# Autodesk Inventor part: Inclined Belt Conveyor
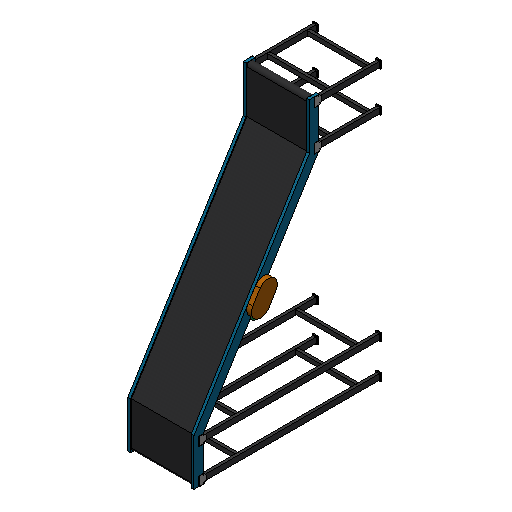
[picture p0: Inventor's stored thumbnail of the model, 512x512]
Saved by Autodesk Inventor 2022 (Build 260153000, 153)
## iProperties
ConnectorClass: Conveyor
family_type: inclined
Created: 2009-10
Part Number: Inclined Belt Conveyor
Document SubType Name: Modeling
Density: 1 g/cm^3
Mass: 74915.2 g
Surface Area: 52834.5 cm^2
Volume: 74915.2 cm^3
Material: 一般
Appearance: 既定
Key Parameters: Width=710.000 mm;UpperHeight=2000.000 mm;LowerHeight=762.000 mm;Length=3000.000 mm;UpperFloatingHeight=0.000 mm;UpperRungNumber=2.000 ul;LowerRungNumber=2.000 u
Title: Inclined Belt Conveyor
Author: Autodesk, Inc.
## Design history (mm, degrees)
body "Solid1"
sketch "Sketch1"
  geometry: L1 (-325, 0)-(325, 0); 2 further points
  constraints: 2 end point, 1 coincident, 1 horizontal, 1 midpoint
  dimensions: "d0" = 650 distance of L1.start L1.end (derived)
workplane "Work Plane1"
sketch "Sketch2"
  geometry: L1 (0, 0)-(0, 2000); L2 (0, 0)-(3000, 0); L3 (3000, 0)-(3000, 762); L4 (0, 2000)-(500, 2000); L5 (500, 2000)-(2500, 762); L6 (2500, 762)-(3000, 762); L7 (0, 2000)-(0, 1900); L8 (3000, 762)-(3000, 662); L9 (471.554, 1900)-(2471.554, 662); L10 (471.554, 1900)-(0, 1900); L11 (2471.554, 662)-(3000, 662)
  constraints: 22 end point, 4 perpendicular, 3 parallel, 2 point on line, 1 vertical
  dimensions: "d1" = 2000 distance of L1.start L1.end (derived); "d2" = 762 distance of L2.end L3.end (derived); "d4" = 500 distance of L1.end L4.end (= EndLength); "d5" = 500 distance of L5.end L3.end (= EndLength); "d6" = 100 distance of L1.end L7.end (= RailHeight); "d7" = 100 distance of L3.end L8.end (= d6); "d8" = 100 distance between parallel lines of L5 L9 (= RailHeight); "d217" = 3000 distance between parallel lines of L3 L1 (derived)
extrude "Rail_1" new body sketch "Sketch2" distance "d9" = 30 (= RailThickness); taper "d10" = 0 deg
mirror "Rail_2"
sketch "Sketch3"
  geometry: L1 (-1288, -2419.054)-(-1288, -2471.554); L2 (-50, 475.946)-(-50, 528.446); L3 (-1288, -2419.054)-(-1288, -1985.777); L4 (-1288, -1985.777)-(-50, 14.223); L5 (-50, 14.223)-(-50, 475.946); L6 (-1238, -2471.554)-(-1338, -2471.554) reference; L7 (0, 0)-(-1238, -2000) reference; L8 (0, 528.446)-(0, 0) reference; L9 (-100, 528.446)-(0, 528.446) reference; L10 (-1238, -2000)-(-1238, -2471.554) reference; L11 (-1338, -1971.554)-(-100, 28.446) reference; L12 (-1338, -2471.554)-(-1338, -1971.554) reference; L13 (-1238, -2471.554)-(-1338, -2471.554) reference; L14 (-1238, -2000)-(-1238, -2471.554) reference; L15 (0, 0)-(-1238, -2000) reference; L16 (0, 528.446)-(0, 0) reference; L17 (-100, 528.446)-(0, 528.446) reference; L18 (-100, 28.446)-(-100, 528.446) reference; L19 (-1338, -1971.554)-(-100, 28.446) reference; L20 (-1238, -2000)-(-1338, -1971.554); L21 (0, 0)-(-100, 28.446); C1 r 30 at (-1288, -2419.054); C2 r 30 at (-50, 475.946); 1 further point
  constraints: 14 end point, 3 midpoint, 3 parallel, 2 centre point, 2 perpendicular
  dimensions: "d11" = 60 diameter of C1; "d12" = 52.5 distance of L1.start L1.end (= 0.5 x RollerGap); "d13" = 60 diameter of C2; "d14" = 52.5 distance of L2.start L2.end (= 0.5 x RollerGap); "StartLength" = 433.27717 distance of L1.start L3.end (derived); "MiddleLength" = 2352.15731 distance of L3.end L4.end (derived); "EndLenght" = 461.72283 distance of L4.end L2.start (derived)
sketch "Sketch6"
  geometry: L1 (0, 0)-(-30, 0) reference; L2 (0, 471.554)-(-30, 471.554) reference; L3 (-29.5, 20)-(-0.5, 20); L4 (-0.5, 20)-(-0.5, 80); L5 (-0.5, 80)-(-29.5, 80); L6 (-29.5, 80)-(-29.5, 20); L7 (-29.5, 391.554)-(-0.5, 391.554); L8 (-0.5, 391.554)-(-0.5, 451.554); L9 (-0.5, 451.554)-(-29.5, 451.554); L10 (-29.5, 451.554)-(-29.5, 391.554); 3 further points
  constraints: 16 end point, 4 parallel, 3 collinear, 2 horizontal, 2 midpoint, 2 perpendicular, 1 vertical alignment
  dimensions: "d18" = 20 distance between parallel lines of L1 L3; "d19" = 60 distance of L5.end L3.start; "d20" = 29 distance of L4.end L5.end; "d21" = 20 distance between parallel lines of L2 L9 (= d18)
workplane "Work Plane3"
extrude "UpperLeg_1" join sketch "Sketch6" taper "d24" = 0 deg; stored distance "d161" = 10
sketch "Sketch7"
  geometry: L1 (0, 0)-(-30, 0) reference; L2 (0, 528.446)-(-30, 528.446) reference; L3 (-29.5, 20)-(-0.5, 20); L4 (-0.5, 20)-(-0.5, 80); L5 (-0.5, 80)-(-29.5, 80); L6 (-29.5, 80)-(-29.5, 20); L7 (-29.5, 448.446)-(-0.5, 448.446); L8 (-0.5, 448.446)-(-0.5, 508.446); L9 (-0.5, 508.446)-(-29.5, 508.446); L10 (-29.5, 508.446)-(-29.5, 448.446); 3 further points
  constraints: 16 end point, 4 parallel, 3 collinear, 2 horizontal, 2 midpoint, 2 perpendicular, 1 vertical alignment
  dimensions: "d25" = 20 distance between parallel lines of L2 L9; "d26" = 60 distance of L9.end L7.start; "d27" = 29 distance of L7.start L7.end; "d28" = 20 distance between parallel lines of L1 L3
workplane "Work Plane4"
extrude "LowerLeg_1" join sketch "Sketch7" taper "d30" = 0 deg; stored distance "d162" = 10
sketch "Sketch8"
  geometry: L1 (0, 60)-(0, 0) reference; L2 (29, 60)-(0, 60) reference; L3 (0, 431.554)-(0, 371.554) reference; L4 (0, 371.554)-(29, 371.554) reference; L5 (29, 371.554)-(29, 431.554) reference; L6 (29, 431.554)-(0, 431.554) reference; L7 (-10.5, -10)-(39.5, -10); L8 (39.5, -10)-(39.5, 70); L9 (39.5, 70)-(-10.5, 70); L10 (-10.5, 70)-(-10.5, -10); L11 (-10.5, 361.554)-(39.5, 361.554); L12 (39.5, 361.554)-(39.5, 441.554); L13 (39.5, 441.554)-(-10.5, 441.554); L14 (-10.5, 441.554)-(-10.5, 361.554); 9 further points
  constraints: 16 end point, 8 midpoint, 4 parallel, 2 horizontal, 2 horizontal alignment, 2 perpendicular, 2 vertical alignment
  dimensions: "d31" = 80 distance of L9.end L7.start; "d32" = 50 distance of L8.end L9.end; "d33" = 80 distance of L13.end L11.start; "d34" = 50 distance of L12.end L13.end
extrude "UpperLeg_2" join sketch "Sketch8" distance "d35" = 10; taper "d36" = 0 deg
sketch "Sketch9"
  geometry: L1 (0, 60)-(0, 0) reference; L2 (0, 0)-(29, 0) reference; L3 (0, 488.446)-(0, 428.446) reference; L4 (0, 428.446)-(29, 428.446) reference; L5 (29, 428.446)-(29, 488.446) reference; L6 (29, 488.446)-(0, 488.446) reference; L7 (-10.5, -10)-(39.5, -10); L8 (39.5, -10)-(39.5, 70); L9 (39.5, 70)-(-10.5, 70); L10 (-10.5, 70)-(-10.5, -10); L11 (-10.5, 418.446)-(39.5, 418.446); L12 (39.5, 418.446)-(39.5, 498.446); L13 (39.5, 498.446)-(-10.5, 498.446); L14 (-10.5, 498.446)-(-10.5, 418.446); 9 further points
  constraints: 16 end point, 8 midpoint, 4 parallel, 2 horizontal, 2 horizontal alignment, 2 perpendicular, 2 vertical alignment
  dimensions: "d37" = 80 distance of L9.end L7.start; "d38" = 50 distance of L8.end L9.end; "d39" = 80 distance of L13.end L11.start; "d40" = 50 distance of L12.end L13.end
extrude "LowerLeg_2" join sketch "Sketch9" distance "d41" = 10; taper "d42" = 0 deg
mirror "OthersideLeg"
sketch "Sketch10"
  geometry: L1 (0, 0)-(0, 60) reference; L2 (0, 431.554)-(0, 371.554) reference; L3 (-1890, 371.554)-(0, 371.554) reference; L4 (-1890, 431.554)-(-1890, 371.554) reference; L5 (-1890, 431.554)-(0, 431.554) reference; L6 (0, 2531.554)-(0, 2471.554) reference; L7 (-652, 2471.554)-(0, 2471.554) reference; L8 (-652, 2531.554)-(-652, 2471.554) reference; L9 (-652, 2531.554)-(0, 2531.554) reference; L10 (0, 2960)-(0, 2900) reference; L11 (-652, 2900)-(0, 2900) reference; L12 (-652, 2960)-(-652, 2900) reference; L13 (-652, 2960)-(0, 2960) reference; L14 (-219, 7.5)-(-189, 7.5); L15 (-189, 7.5)-(-189, 52.5); L16 (-189, 52.5)-(-219, 52.5); L17 (-219, 52.5)-(-219, 7.5); L18 (-219, 379.054)-(-189, 379.054); L19 (-189, 379.054)-(-189, 424.054); L20 (-189, 424.054)-(-219, 424.054); L21 (-219, 424.054)-(-219, 379.054); L22 (-95.2, 2479.054)-(-65.2, 2479.054); L23 (-65.2, 2479.054)-(-65.2, 2524.054); L24 (-65.2, 2524.054)-(-95.2, 2524.054); L25 (-95.2, 2524.054)-(-95.2, 2479.054); L26 (-95.2, 2907.5)-(-65.2, 2907.5); L27 (-65.2, 2907.5)-(-65.2, 2952.5); L28 (-65.2, 2952.5)-(-95.2, 2952.5); L29 (-95.2, 2952.5)-(-95.2, 2907.5); L30 (-1890, 0)-(-1890, 60) reference; L31 (-1890, 0)-(0, 0) reference; L32 (-1890, 30)-(-1512, 30); L33 (-1512, 30)-(-219, 30); 9 further points
  constraints: 36 end point, 10 midpoint, 9 parallel, 6 collinear, 4 horizontal, 4 horizontal alignment, 4 perpendicular
  dimensions: "d43" = 189 distance between parallel lines of L1 L15 (derived); "d44" = 30 distance of L15.end L16.end; "d45" = 45 distance of L16.end L14.start; "d46" = 65.2 distance between parallel lines of L6 L23 (derived); "d47" = 45 distance of L24.end L22.start; "d48" = 30 distance of L23.end L24.end; "d225" = 378 distance of L32.start L32.end (derived); "StartRungDistance" = 1293 distance of L32.end L33.end (derived)
extrude "UpperLeg_3" join sketch "Sketch10" taper "d49" = 0 deg; stored distance "d163" = 10
pattern_linear "UpperLeg_4" dims "d52" = 1293 (derived)
sketch "Sketch12"
  geometry: L1 (-95.2, -375.946)-(-95.2, -420.946) reference; L2 (-65.2, -420.946)-(-65.2, -375.946) reference; L3 (-65.2, -375.946)-(-95.2, -375.946) reference; L4 (-95.2, -420.946)-(-65.2, -420.946) reference; L5 (-65.2, 7.5)-(-65.2, 52.5) reference; L6 (-95.2, 7.5)-(-65.2, 7.5) reference; L7 (-95.2, 52.5)-(-95.2, 7.5) reference; L8 (-65.2, 52.5)-(-95.2, 52.5) reference; L9 (-652, 0)-(-652, 60) reference; L10 (-652, 0)-(0, 0) reference; L11 (-652, 30)-(-521.6, 30); L12 (-521.6, 30)-(-95.2, 30); 1 further point
  constraints: 4 end point, 2 midpoint, 1 parallel
  dimensions: "d227" = 130.4 distance of L11.start L11.end (derived); "EndRungDistance" = 426.4 distance of L11.end L12.end (derived)
extrude "LowerLeg_3" join sketch "Sketch12" taper "d53" = 0 deg; stored distance "d165" = 10
pattern_linear "LowerLeg_4" dims "d56" = 426.4 (derived)
sketch "Sketch19"
  geometry: L1 (-1950, 485.777)-(-712, 2485.777); L2 (-1271.076, 1431.957)-(-1295.121, 1446.841); L3 (-1271.076, 1431.957)-(-1381, 1500); L4 (-1295.121, 1446.841)-(-1381, 1500); L5 (-1334.596, 1383.07)-(-1255.647, 1510.612); L6 (-1249.567, 1330.437)-(-1170.619, 1457.98); L7 (-1419.624, 1435.702)-(-1340.675, 1563.245); L8 (-2000, 500)-(-762, 2500) reference; L9 (-662, 2471.554)-(-1900, 471.554) reference; L10 (-1900, 471.554)-(-2000, 500); L11 (-662, 2471.554)-(-762, 2500); A1 r 75 centre (-1255.647, 1510.612) between (-1320.104, 1548.957) and (-1295.121, 1446.841); A2 r 100 centre (-1255.647, 1510.612) between (-1170.619, 1457.98) and (-1340.675, 1563.245); A3 r 100 centre (-1334.596, 1383.07) between (-1419.624, 1435.702) and (-1249.567, 1330.437); A4 r 75 centre (-1334.596, 1383.07) between (-1295.121, 1446.841) and (-1401.494, 1416.975); 1 further point
  constraints: 18 end point, 8 point on circle, 5 parallel, 4 centre point, 4 midpoint, 2 coincident, 2 collinear, 2 tangent, 1 perpendicular
  dimensions: "d57" = 101 distance of L2.end L3.end (derived); "d58" = 150 distance of L5.start L5.end; "d61" = 100 radius of A3; "d62" = 100 radius of A2
extrude "Center-Left_1" join sketch "Sketch19" distance "d63" = 50; taper "d64" = 0 deg
sketch "Sketch20"
  geometry: L1 (1249.567, 1330.437)-(1170.619, 1457.98) reference; L2 (1284.837, 1446.356)-(1326.943, 1378.333); L3 (1326.943, 1378.333)-(1241.915, 1325.7); L4 (1241.915, 1325.7)-(1199.809, 1393.723); L5 (1199.809, 1393.723)-(1284.837, 1446.356); 9 further points; 1 other entity
  constraints: 9 end point, 3 parallel, 1 perpendicular, 1 point on line, 2 other
  dimensions: "d204" = 10 dimension on L2; "d205" = 80 distance of L3.end L4.end; "d206" = 100 distance of L4.end L2.start
extrude "Center-Left_2" join sketch "Sketch20" distance "d67" = 100; taper "d68" = 0 deg
sketch "Sketch42"
  geometry: L1 (0, 100)-(0, 0) reference; L2 (100, 0)-(0, 0) reference; L3 (100, 100)-(0, 100) reference; C1 r 50 at (50, 50); 1 further point
  constraints: 3 tangent, 1 centre point
extrude "Center-Left_3" join sketch "Sketch42" distance "d207" = 80; taper "d208" = 0 deg
sketch "Sketch43"
  geometry: C1 r 15 at (0, 0); 3 further points
  constraints: 1 centre point, 1 coincident, 1 horizontal alignment
  dimensions: "d209" = 30 diameter of C1
extrude "Center-Left_4" join sketch "Sketch43" distance "d210" = 20; taper "d211" = 0 deg
sketch "Sketch44"
  geometry: C1 r 15 at (0, 0) reference; C2 r 40 at (0, 0); 1 further point
  constraints: 1 centre point, 1 coincident
  dimensions: "d212" = 80 diameter of C2
extrude "Center-Left_5" join sketch "Sketch44" distance "d213" = 30; taper "d214" = 0 deg
sketch "Sketch30"
  geometry: L1 (0, 0)-(0, 60) reference; L2 (1890, 431.554)-(1890, 371.554) reference; L3 (0, 431.554)-(1890, 431.554) reference; L4 (0, 371.554)-(0, 431.554) reference; L5 (0, 371.554)-(1890, 371.554) reference; L6 (1890, 2531.554)-(1890, 2471.554) reference; L7 (1238, 2531.554)-(1890, 2531.554) reference; L8 (1238, 2471.554)-(1238, 2531.554) reference; L9 (1238, 2471.554)-(1890, 2471.554) reference; L10 (1890, 2960)-(1890, 2900) reference; L11 (1238, 2960)-(1890, 2960) reference; L12 (1238, 2900)-(1238, 2960) reference; L13 (1238, 2900)-(1890, 2900) reference; L14 (0, -20)-(-100, -20) reference; L15 (1138, 2980)-(1238, 2980) reference; L16 (2.45, -19)-(30, 10); L17 (30, 10)-(30, 50); L18 (30, 50)-(2.45, 79); L19 (2.45, 79)-(-50, 79); L20 (-50, 79)-(-50, -19); L21 (-50, -19)-(2.45, -19); L22 (30, 381.554)-(30, 421.554); L23 (30, 421.554)-(2.45, 447.727); L24 (2.45, 447.727)-(-50, 447.727); L25 (-50, 447.727)-(-50, 355.382); L26 (-50, 355.382)-(2.45, 355.382); L27 (2.45, 355.382)-(30, 381.554); L28 (1268, 2910)-(1268, 2950); L29 (1240.45, 2979)-(1188, 2979); L30 (1188, 2979)-(1188, 2881); L31 (1188, 2881)-(1240.45, 2881); L32 (1268, 2481.554)-(1268, 2521.554); L33 (1268, 2521.554)-(1240.45, 2550.554); L34 (1240.45, 2550.554)-(1188, 2550.554); L35 (1188, 2550.554)-(1188, 2452.554); L36 (1188, 2452.554)-(1240.45, 2452.554); L37 (1240.45, 2452.554)-(1268, 2481.554); L38 (1268, 2910)-(1240.45, 2881); L39 (1268, 2950)-(1240.45, 2979); 14 further points
  constraints: 48 end point, 13 midpoint, 12 equal length, 9 perpendicular, 8 horizontal alignment, 5 parallel, 3 collinear, 1 vertical alignment
  dimensions: "d76" = 40 distance of L16.end L17.end; "d77" = 1 distance between parallel lines of L14 L21; "d78" = 30 distance between parallel lines of L1 L17; "d79" = 40 distance of L16.start L16.end; "d80" = 1 distance between parallel lines of L15 L29; "d81" = 30 distance between parallel lines of L28 L12; "d224" = 30 distance between parallel lines of L32 L8
extrude "BracingPlate_1" join sketch "Sketch30" distance "d82" = 5; taper "d83" = 0 deg
mirror "BracingPlate_2"
sketch "Sketch31"
  geometry: L1 (-1288, 2485.777)-(-50, 485.777); L2 (-619, 1500)-(-704.879, 1446.841); L3 (-744.353, 1510.612)-(-665.404, 1383.07); L4 (-659.325, 1563.245)-(-580.376, 1435.702); L5 (-829.381, 1457.98)-(-750.433, 1330.437); L6 (0, 500)-(-1238, 2500) reference; L7 (-1338, 2471.554)-(-100, 471.554) reference; L8 (-1338, 2471.554)-(-1238, 2500); L9 (-100, 471.554)-(0, 500); A1 r 100 centre (-744.353, 1510.612) between (-659.325, 1563.245) and (-829.381, 1457.98); A2 r 100 centre (-665.404, 1383.07) between (-750.433, 1330.437) and (-580.376, 1435.702); 1 further point
  constraints: 14 end point, 4 midpoint, 4 point on circle, 4 tangent, 2 centre point, 2 coincident, 2 perpendicular, 1 parallel
  dimensions: "d87" = 150 distance of L3.start L3.end; "d88" = 100 radius of A1; "d89" = 100 radius of A2; "d229" = 101 distance of L2.start L2.end
extrude "Center-Right_1" join sketch "Sketch31" distance "d90" = 50; taper "d91" = 0 deg
sketch "Sketch32"
  geometry: L1 (797.202, 1596.035)-(612.778, 1298.577) reference; L2 (830.351, 1457.828)-(751.31, 1330.342) reference; L3 (673.969, 1378.294)-(716.124, 1446.286); L4 (716.124, 1446.286)-(801.114, 1393.592); L5 (801.114, 1393.592)-(758.959, 1325.6); L6 (758.959, 1325.6)-(673.969, 1378.294); A1 r 100 centre (666.32, 1383.036) between (612.778, 1298.577) and (751.31, 1330.342) reference; 1 further point
  constraints: 8 end point, 3 parallel, 1 perpendicular, 1 point on line
  dimensions: "d193" = 10 distance between parallel lines of L3 L1; "d194" = 100 distance of L3.end L4.end; "d195" = 80 distance of L4.end L5.end
extrude "Center-Right_2" join sketch "Sketch32" distance "d94" = 100; taper "d95" = 0 deg
sketch "Sketch39"
  geometry: L1 (100, -100)-(100, 0) reference; L2 (0, 0)-(100, 0) reference; L3 (0, -100)-(100, -100) reference; C1 r 50 at (50, -50); 1 further point
  constraints: 3 tangent, 1 centre point
extrude "Center-Right_3" join sketch "Sketch39" distance "d196" = 80; taper "d197" = 0 deg
sketch "Sketch40"
  geometry: C1 r 15 at (0, 0); 3 further points
  constraints: 1 centre point, 1 coincident, 1 horizontal alignment
  dimensions: "d198" = 30 diameter of C1
extrude "Center-Right_4" join sketch "Sketch40" distance "d199" = 20; taper "d200" = 0 deg
sketch "Sketch41"
  geometry: C1 r 15 at (0, 0) reference; C2 r 40 at (0, 0); 1 further point
  constraints: 1 centre point, 1 coincident
  dimensions: "d201" = 80 diameter of C2
extrude "Center-Right_5" join sketch "Sketch41" distance "d202" = 30; taper "d203" = 0 deg
sketch "Sketch36"
  geometry: L1 (-1338, -1971.554)-(-1238, -2000); L2 (-1238, -2471.554)-(-1338, -2471.554) reference; L3 (-100, 528.446)-(0, 528.446) reference; L4 (-1288, -2431.554)-(-1288, -2471.554); L5 (-50, 488.446)-(-50, 528.446); L6 (-1328, -2431.554)-(-1328, -1974.399); L7 (-1326, -2431.554)-(-1326, -1974.968); L8 (-1248, -2431.554)-(-1248, -1997.155); L9 (-1250, -2431.554)-(-1250, -1996.587); L10 (-90, 488.446)-(-90, 25.601); L11 (-10, 488.446)-(-10, 2.845); L12 (-12, 488.446)-(-12, 3.413); L13 (-88, 488.446)-(-88, 25.032); L14 (-1328, -1974.399)-(-90, 25.601); L15 (-88, 25.032)-(-1326, -1974.968); L16 (-1248, -1997.155)-(-10, 2.845); L17 (-12, 3.413)-(-1250, -1996.587); L18 (-1338, -2471.554)-(-1338, -1971.554) reference; L19 (-100, 28.446)-(0, 0); C1 r 40 at (-1288, -2431.554); C2 r 40 at (-50, 488.446); A1 r 40 centre (-1288, -2431.554) between (-1328, -2431.554) and (-1248, -2431.554); A2 r 40 centre (-50, 488.446) between (-10, 488.446) and (-90, 488.446); A3 r 38 centre (-1288, -2431.554) between (-1326, -2431.554) and (-1250, -2431.554); A4 r 38 centre (-50, 488.446) between (-12, 488.446) and (-88, 488.446); 1 further point
  constraints: 32 end point, 14 tangent, 12 parallel, 8 point on circle, 7 point on line, 6 centre point, 3 coincident, 2 midpoint, 2 perpendicular, 1 concentric
  dimensions: "d185" = 80 diameter of C1 (derived); "d186" = 40 distance of L4.start L4.end (derived); "d188" = 40 distance of L5.start L5.end (= d186); "d189" = 80 diameter of C2 (= d185); "d244" = 2 radial gap between concentric circles of A1 A3
extrude "Belt" join sketch "Sketch36" stored distance "d173" = 10; taper "d174" = 0 deg
sketch "Landing Surface_Sketch"
  geometry: L1 (-325, 0)-(-355, 0) reference; L2 (325, 3000)-(355, 3000) reference; L3 (-355, 0)-(355, 0); L4 (355, 0)-(355, 3000); L5 (355, 3000)-(-355, 3000); L6 (-355, 3000)-(-355, 0); L7 (355, 0)-(-355, 3000); L8 (355, 3000)-(-355, 0); 2 further points
  constraints: 12 end point, 2 parallel, 1 horizontal, 1 midpoint, 1 perpendicular
node "Connector1_Work Point"
node "Connector2_Work Point"
node "Landing Surface"
node "Connector1"
node "Connector2"
node "Insertion Point1"
workplane "Work Plane2"
node "Projected Loop1"
node "Projected Loop2"
node "Projected Loop3"
node "Projected Loop4"
node "Projected Loop5"
node "Projected Loop7"
node "Projected Loop8"
node "Projected Loop9"
other parameters: "RollerRange" = 3247.15731 (= MiddleLength + StartLength + EndLenght) [user parameter], "RollerNumber" = 309.25308 [user parameter], "d22" = 0 (derived), "d50" = 733.035 (derived), "EndLength" = 500 [user parameter; used in 2 equation terms], "RailHeight" = 100 [user parameter; used in 2 equation terms], "RailThickness" = 30 [user parameter; used in 1 equation term], "RollerGap" = 105 [user parameter; used in 2 equation terms], "AllLevelLength" = 2732.05081 (derived), "d218" = 733 (derived), "d245" = 0, "d246" = 0, "d248" = 0, "d249" = 0, "d250" = 90 deg, "d251" = 0, "d253" = 762, "d254" = 0, "d255" = 0, "d256" = -90 deg
